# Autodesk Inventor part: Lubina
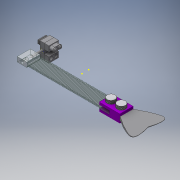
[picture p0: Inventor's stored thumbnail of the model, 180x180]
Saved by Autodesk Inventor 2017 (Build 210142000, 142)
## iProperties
Part Number: Lubina
Material: Genérico
Document SubType Name: Modeling
Designer: Diego
Density: 1 g/cm^3
Appearance: Valor por defecto
Author: Diego
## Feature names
1. Extrusión1
2. Extrusión2
3. Simetría1 [Mirror]
4. Dividir1
5. Dividir2
6. Extrusión3
7. Empalme1 [Fillet]
8. Extrusión4
9. Extrusión5
10. Extrusión14
11. Extrusión15
12. Extrusión16
13. Extrusión17
14. Extrusión18
15. Extrusión19
16. Extrusión20
17. Extrusión21
18. Extrusión22
19. Extrusión23
20. Extrusión24
21. Extrusión25
22. Extrusión26
23. Chaflán1 [Chamfer]
24. Revolución1
25. Patrón rectangular1 [Rectangular Pattern]
26. Revolución2
27. Extrusión27
28. Patrón rectangular3 [Rectangular Pattern]
29. Simetría3 [Mirror]
30. Extrusión28
31. Simetría4 [Mirror]
32. Extrusión29
33. Simetría5 [Mirror]
34. Extrusión30
35. Extrusión31
36. Patrón rectangular4 [Rectangular Pattern]
37. Extrusión32
38. Extrusión33
39. Extrusión34
40. Extrusión35
41. Extrusión36
42. Extrusión37
43. Extrusión38
44. Simetría6 [Mirror]
45. Extrusión39
46. Extrusión40
47. Barrido1
48. Patrón rectangular5 [Rectangular Pattern]
49. Chaflán2 [Chamfer]
50. Extrusión41
## Parameters: d5 = 12 mm, d6 = 12 mm, d14 = 0, d16 = 8 mm, d17 = 8 mm, d73 = 9 mm, d74 = 9 mm, d78 = 5 mm, d79 = 0, d81 = 0.15 mm, d82 = 4 mm, d83 = 4 mm, d84 = 15 mm, d85 = 4 mm, d86 = 4 mm, d87 = 5 mm, d88 = 0, d89 = 0, d90 = 0, d91 = -0.15 mm, d92 = 3 mm, d93 = 6 mm, d94 = 6 mm, d96 = 0, d98 = 0, d133 = 0.15 mm, d134 = 0.15 mm, d136 = 4.85 mm, d137 = 0, d138 = 7.5 mm, d139 = 7.5 mm, d140 = 3.75 mm, d141 = 4 mm, d142 = 4 mm, d143 = 4.85 mm, d144 = 0, d145 = 4.85 mm, d146 = 0, d147 = 4.85 mm, d148 = 0, d149 = 1 mm, d150 = 0, d151 = 14 mm, d152 = 0, d153 = 0.15 mm, d154 = 0.15 mm, d155 = 3 mm, d157 = 0, d158 = 3.5 mm, d159 = 14 mm, d160 = 3.5 mm, d162 = 0, d163 = 4 mm, d164 = 3.5 mm, d165 = 0.2 mm, d166 = 7.5 mm, d167 = 0, d168 = 7 mm, d169 = 0, d170 = 5 mm, d171 = 0, d172 = 0.15 mm, d173 = 0.15 mm, d174 = 0.15 mm, d175 = 0.15 mm, d176 = 12 mm, d177 = 5 mm, d178 = 0, d179 = 1 mm, d180 = 0, d181 = 1 mm, d182 = 2 mm, d183 = 45 deg, d184 = 0.5 mm, d185 = 90 deg, d188 = -1 mm, d192 = 90 deg, d193 = 5 mm, d194 = 5 mm, d195 = 90 deg, d205 = 0.5 mm, d206 = 1 mm, d207 = 1 mm, d208 = 0.5 mm, d209 = 0.5 mm, d211 = 0, d212 = 2 mm, d213 = 0, d214 = 0, d220 = 2 mm, d221 = 53 mm, d222 = 0.5 mm, d223 = 1 mm, d224 = 1 mm, d225 = 0.5 mm, d226 = 0.5 mm, d228 = 0, d230 = 1 mm, d231 = 1 mm, d232 = 0.25 mm, d233 = 53 mm, d234 = 0.5 mm, d235 = 0.25 mm, d239 = 0, d241 = 0, d242 = 0.25 mm, d243 = 0.25 mm, d245 = 0, d248 = 15 mm, d249 = 0.25 mm, d250 = 6 mm, d252 = 0, d263 = 8 mm, d264 = 14 mm, d265 = 5 mm, d266 = 5 mm, d267 = 6 mm, d268 = 0, d269 = 6 mm, d270 = 0, d271 = 6 mm, d272 = 0, d273 = 0.5 mm, d274 = 0, d275 = 0.5 mm, d276 = 0, d277 = 6.9 mm, d278 = 0, d279 = 0.15 mm, d280 = 0.15 mm, d282 = 0, d283 = 5 mm, d284 = 0, d285 = 1 mm, d286 = 0, d287 = 0, d290 = 2 mm, d291 = 1 mm, d292 = 2 mm, d293 = 45 deg, d294 = 6 mm, d295 = 6 mm, d296 = 5 mm, d297 = 0
